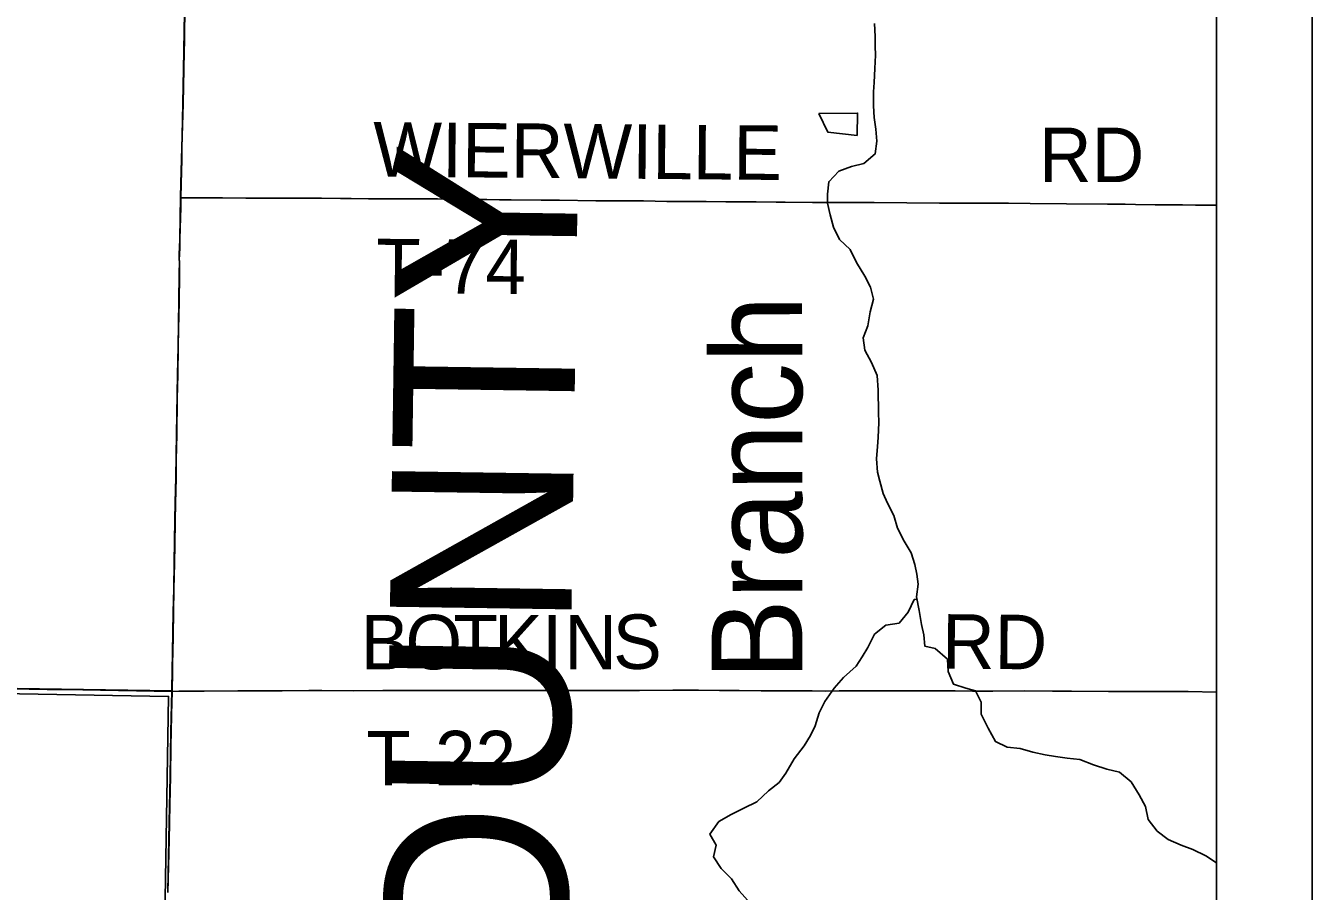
# Model space of a CAD drawing. Extents: x 0 to 34, y 0 to 22.
# Drawn here: x 7.658 to 9, y 19.194 to 20.097 of the extents above; entities that cross this region are included whole.
import ezdxf

# ---------------------------------------------------------------- set-up
doc = ezdxf.new("R2010")
doc.units = 0
for name, color, linetype in [('GM_X_Corporation', 7, 'Continuous'), ('GM_X_County_Road', 7, 'Continuous'), ('GM_X_County_Text', 7, 'Continuous'), ('GM_X_Minor_Lake', 7, 'Continuous'), ('GM_X_Minor_River', 7, 'Continuous'), ('GM_X_Minor_River_Text', 7, 'Continuous'), ('GM_X_Township_Road', 7, 'Continuous'), ('GM_X_Township_Road_Text', 7, 'Continuous'), ('SH_Data', 7, 'Continuous')]:
    doc.layers.add(name, color=color, linetype=linetype)

msp = doc.modelspace()

# ---------------------------------------------------------------- linework, layer by layer
at = {"layer": 'GM_X_Corporation'}
for points in [[(8.9, 14.1), (8.9, 20.4201)], [(8.9, 16.4207), (8.9, 20.4201)], [(6.935, 19.4163), (7.8106, 19.4031), (7.8106, 19.4051), (7.8112, 19.443), (7.812, 19.4853), (7.8125, 19.5095), (7.8131, 19.5368), (7.8137, 19.581), (7.8141, 19.5996), (7.8146, 19.6257), (7.8154, 19.671), (7.8164, 19.7332), (7.817, 19.7624), (7.8178, 19.8096), (7.8183, 19.8376), (7.8185, 19.8513), (7.8181, 19.8532), (7.8181, 19.8549), (7.8181, 19.8598), (7.8186, 19.8654), (7.8188, 19.8747), (7.8194, 19.897), (7.8197, 19.918), (7.82, 19.9325), (7.8207, 19.9579), (7.8212, 19.9822), (7.8219, 20.0157), (7.8232, 20.0704), (7.8235, 20.0928), (7.8238, 20.1089)], [(7.8238, 20.1089), (7.8235, 20.0928), (7.8232, 20.0704), (7.8219, 20.0157), (7.8212, 19.9822), (7.8207, 19.9579), (7.82, 19.9325), (7.8197, 19.918), (7.8194, 19.897), (7.8188, 19.8747), (7.8186, 19.8654), (7.8181, 19.8598), (7.8181, 19.8549), (7.8181, 19.8532), (7.8185, 19.8513), (7.8183, 19.8376), (7.8178, 19.8096), (7.817, 19.7624), (7.8164, 19.7332), (7.8154, 19.671), (7.8146, 19.6257), (7.8141, 19.5996), (7.8137, 19.581), (7.8131, 19.5368), (7.8125, 19.5095), (7.812, 19.4853), (7.8112, 19.443), (7.8106, 19.4051), (7.8106, 19.4031), (7.8096, 19.3604), (7.8087, 19.3138), (7.8077, 19.2659), (7.8062, 19.1933)], [(7.8062, 19.1933), (7.8077, 19.2659), (7.8087, 19.3138), (7.8096, 19.3604), (7.8106, 19.4031), (7.8106, 19.4051), (7.8112, 19.443), (7.812, 19.4853), (7.8125, 19.5095), (7.8131, 19.5368), (7.8137, 19.581), (7.8141, 19.5996), (7.8146, 19.6257), (7.8154, 19.671), (7.8164, 19.7332), (7.817, 19.7624), (7.8178, 19.8096), (7.8183, 19.8376), (7.8185, 19.8513), (7.8181, 19.8532), (7.8181, 19.8549), (7.8181, 19.8598), (7.8186, 19.8654), (7.8188, 19.8747), (7.8194, 19.897), (7.8197, 19.918), (7.82, 19.9325), (7.8207, 19.9579), (7.8212, 19.9822), (7.8219, 20.0157), (7.8232, 20.0704), (7.8235, 20.0928), (7.8238, 20.1089)], [(7.8238, 20.1089), (7.8235, 20.0928), (7.8232, 20.0704), (7.8219, 20.0157), (7.8212, 19.9822), (7.8207, 19.9579), (7.82, 19.9325), (7.8197, 19.918), (7.8194, 19.897), (7.8188, 19.8747), (7.8186, 19.8654), (7.8181, 19.8598), (7.8181, 19.8549), (7.8181, 19.8532), (7.8185, 19.8513), (7.8183, 19.8376), (7.8178, 19.8096), (7.817, 19.7624), (7.8164, 19.7332), (7.8154, 19.671), (7.8146, 19.6257), (7.8141, 19.5996), (7.8137, 19.581), (7.8131, 19.5368), (7.8125, 19.5095), (7.812, 19.4853), (7.8112, 19.443), (7.8106, 19.4051), (7.8106, 19.4031), (7.8096, 19.3604), (7.8087, 19.3138), (7.8077, 19.2659), (7.8062, 19.1933)], [(7.8062, 19.1933), (7.8077, 19.2659), (7.8087, 19.3138), (7.8096, 19.3604), (7.8106, 19.4031), (6.935, 19.4163), (6.733, 19.4196), (6.6989, 19.42), (5.8089, 19.4308), (5.2195, 19.4431), (4.8049, 19.4497), (4.7562, 19.4505)]]:
    msp.add_lwpolyline(points, dxfattribs=at)
msp.add_lwpolyline([(6.7967, 19.4154), (7.8071, 19.3973), (7.7914, 18.4475), (7.7907, 18.396), (6.7843, 18.4413), (6.7907, 19.4159)], close=True, dxfattribs=at)
at = {"layer": 'GM_X_County_Road'}
msp.add_line((7.82, 19.9175), (7.8203, 19.9319), dxfattribs=at)
for points in [[(7.8203, 19.9319), (7.8206, 19.9447), (7.8209, 19.9574), (7.8211, 19.9695), (7.8214, 19.9816), (7.8222, 20.0152), (7.8226, 20.0338), (7.8234, 20.0699), (7.8236, 20.081), (7.8238, 20.0922), (7.8241, 20.1084)], [(7.8108, 19.4025), (7.8112, 19.4232), (7.8113, 19.4329), (7.8115, 19.4425), (7.8118, 19.4611), (7.8122, 19.4847), (7.8127, 19.509), (7.8134, 19.5363), (7.8136, 19.5549), (7.8139, 19.5804), (7.8143, 19.599), (7.8149, 19.6251), (7.8152, 19.6438), (7.8156, 19.6705), (7.8162, 19.7078), (7.8165, 19.7202), (7.8167, 19.7326), (7.8172, 19.7618), (7.8176, 19.7805), (7.8178, 19.7948), (7.8181, 19.809), (7.8186, 19.837), (7.8187, 19.8507), (7.8183, 19.8526), (7.8188, 19.8649), (7.819, 19.8742), (7.8193, 19.8853), (7.8196, 19.8965), (7.8198, 19.907), (7.82, 19.9175)], [(7.8064, 19.1927), (7.8076, 19.2477), (7.808, 19.2654), (7.8084, 19.284), (7.809, 19.3132), (7.8096, 19.3459), (7.8099, 19.3598), (7.8103, 19.3785), (7.8108, 19.4025)]]:
    msp.add_lwpolyline(points, dxfattribs=at)
at = {"layer": 'GM_X_Minor_Lake'}
for points in [[(8.5252, 19.9825), (8.5257, 20.0059), (8.4852, 20.0053)], [(8.4852, 20.0053), (8.4948, 19.9859), (8.5252, 19.9825)]]:
    msp.add_lwpolyline(points, dxfattribs=at)
at = {"layer": 'GM_X_Minor_River'}
for points in [[(8.5435, 20.0994), (8.544, 20.0857), (8.5442, 20.0758), (8.5444, 20.0663), (8.5437, 20.0523), (8.5431, 20.0378), (8.5425, 20.028), (8.5422, 20.0135), (8.5431, 20.0013), (8.5448, 19.9891), (8.5457, 19.9766), (8.544, 19.9633), (8.5323, 19.9533), (8.5193, 19.9501), (8.5062, 19.9454), (8.4957, 19.9342), (8.4943, 19.9213), (8.4945, 19.9118), (8.497, 19.8995), (8.5005, 19.8869), (8.5068, 19.8739), (8.518, 19.8634), (8.5247, 19.85), (8.5335, 19.8357), (8.5394, 19.8242), (8.5423, 19.8116), (8.5389, 19.7984), (8.5364, 19.784), (8.5316, 19.7715), (8.5332, 19.7586), (8.5402, 19.7455), (8.5461, 19.7321), (8.5473, 19.7168), (8.5477, 19.6933), (8.5478, 19.683), (8.5472, 19.6674), (8.5466, 19.6579), (8.5456, 19.645), (8.5465, 19.6313), (8.549, 19.6217), (8.5526, 19.6088), (8.557, 19.5988), (8.5636, 19.5861), (8.5675, 19.5727), (8.5745, 19.5593), (8.5816, 19.547), (8.5855, 19.5347), (8.5876, 19.5248), (8.589, 19.5145), (8.5872, 19.5012), (8.59, 19.4867), (8.5924, 19.4722), (8.5948, 19.4616), (8.5958, 19.4497), (8.6068, 19.4473), (8.6195, 19.436), (8.6201, 19.4234), (8.6259, 19.41), (8.6388, 19.406), (8.6487, 19.4031), (8.6546, 19.3912), (8.6547, 19.3787), (8.6621, 19.3641), (8.6695, 19.3502), (8.6819, 19.3443), (8.6953, 19.3429), (8.7086, 19.3389), (8.7215, 19.3363), (8.7321, 19.3346), (8.7443, 19.3329), (8.7577, 19.3315)], [(8.5877, 19.4988), (8.5848, 19.4982), (8.5785, 19.4851), (8.5691, 19.4738), (8.5553, 19.4714), (8.5433, 19.4621), (8.5366, 19.4482), (8.5307, 19.4384), (8.5244, 19.4287), (8.5112, 19.4171), (8.5014, 19.4059), (8.4916, 19.392), (8.4857, 19.38), (8.4816, 19.3667), (8.4765, 19.3566), (8.4701, 19.3456), (8.4596, 19.3322), (8.4509, 19.3171), (8.4439, 19.3074), (8.433, 19.2988), (8.4206, 19.2873), (8.4071, 19.2807), (8.394, 19.2741), (8.3809, 19.2667), (8.3715, 19.2536), (8.3781, 19.242), (8.3756, 19.2299), (8.3834, 19.2176), (8.3943, 19.2068), (8.4024, 19.1944), (8.414, 19.1813)], [(8.7577, 19.3315), (8.7717, 19.3259), (8.7857, 19.3214), (8.799, 19.3181), (8.811, 19.308), (8.8196, 19.2946), (8.8262, 19.2823), (8.829, 19.2689), (8.8383, 19.2566), (8.8496, 19.248), (8.8632, 19.242), (8.8754, 19.2376), (8.889, 19.2309), (8.9, 19.2236)]]:
    msp.add_lwpolyline(points, dxfattribs=at)
at = {"layer": 'GM_X_Township_Road'}
msp.add_line((7.82, 19.9175), (7.8203, 19.9319), dxfattribs=at)
for points in [[(7.8203, 19.9319), (7.8206, 19.9447), (7.8209, 19.9574), (7.8211, 19.9695), (7.8214, 19.9816), (7.8222, 20.0152), (7.8226, 20.0338), (7.8234, 20.0699), (7.8236, 20.081), (7.8238, 20.0922), (7.8241, 20.1084)], [(7.8108, 19.4025), (7.8112, 19.4232), (7.8113, 19.4329), (7.8115, 19.4425), (7.8118, 19.4611), (7.8122, 19.4847), (7.8127, 19.509), (7.8134, 19.5363), (7.8136, 19.5549), (7.8139, 19.5804), (7.8143, 19.599), (7.8149, 19.6251), (7.8152, 19.6438), (7.8156, 19.6705), (7.8162, 19.7078), (7.8165, 19.7202), (7.8167, 19.7326), (7.8172, 19.7618), (7.8176, 19.7805), (7.8178, 19.7948), (7.8181, 19.809), (7.8186, 19.837), (7.8187, 19.8507), (7.8183, 19.8526), (7.8188, 19.8649), (7.819, 19.8742), (7.8193, 19.8853), (7.8196, 19.8965), (7.8198, 19.907), (7.82, 19.9175)], [(7.82, 19.9175), (7.8273, 19.9175), (7.8285, 19.9175), (7.8391, 19.9174), (7.8503, 19.9175), (7.8633, 19.9174), (7.8876, 19.9171), (7.9205, 19.9171), (7.9373, 19.9171), (7.9441, 19.9171), (7.9559, 19.9171), (7.9665, 19.917), (7.9863, 19.9167), (7.9975, 19.9166), (8.0155, 19.9165), (8.0447, 19.9165), (8.0603, 19.9164), (8.0727, 19.9163), (8.0876, 19.9162), (8.1025, 19.916), (8.1174, 19.9158), (8.1391, 19.9155), (8.1522, 19.9153), (8.1646, 19.9152), (8.1957, 19.915), (8.2149, 19.9149), (8.2528, 19.9144), (8.3025, 19.9142), (8.3267, 19.9137), (8.3479, 19.9136), (8.3678, 19.9135), (8.3883, 19.9134), (8.416, 19.9134)], [(8.416, 19.9134), (8.4199, 19.9134), (8.441, 19.913), (8.4503, 19.9129), (8.4789, 19.9127), (8.4976, 19.9127), (8.5274, 19.9124), (8.5429, 19.9124), (8.5771, 19.9122), (8.6112, 19.9118), (8.6479, 19.912), (8.6684, 19.9119), (8.6833, 19.9117), (8.7056, 19.9114), (8.7435, 19.911), (8.7864, 19.9109), (8.805, 19.9107), (8.8156, 19.9105), (8.8361, 19.9102), (8.8578, 19.9101), (8.8647, 19.91), (8.8783, 19.9098), (8.8888, 19.9097), (8.9, 19.9098)], [(7.6431, 19.4052), (7.6617, 19.4049), (7.6804, 19.4046), (7.699, 19.4043), (7.7177, 19.404), (7.7363, 19.4037), (7.755, 19.4034), (7.7736, 19.4031), (7.7922, 19.4028), (7.8108, 19.4025)], [(7.8108, 19.4025), (7.8179, 19.4026), (7.8441, 19.4027), (7.8795, 19.403), (7.9255, 19.403), (7.9534, 19.4033), (7.9671, 19.4035), (8, 19.4031), (8.0305, 19.4033), (8.0522, 19.4034), (8.1001, 19.4033), (8.1311, 19.4033), (8.2237, 19.4033), (8.2573, 19.4033), (8.2815, 19.4035), (8.2983, 19.4035), (8.3331, 19.4036), (8.3598, 19.4036), (8.3816, 19.4034), (8.4021, 19.4033), (8.4251, 19.4032), (8.445, 19.4031), (8.4785, 19.4029), (8.4928, 19.4028), (8.5065, 19.4029), (8.5226, 19.403), (8.5375, 19.403), (8.5562, 19.4029), (8.6022, 19.403), (8.6276, 19.4029), (8.6456, 19.4027), (8.6668, 19.4026), (8.7003, 19.4029), (8.7289, 19.4027), (8.7488, 19.4027), (8.7873, 19.4025), (8.8221, 19.4024), (8.8482, 19.4023), (8.8706, 19.4022), (8.9, 19.4018)], [(7.8064, 19.1927), (7.8076, 19.2477), (7.808, 19.2654), (7.8084, 19.284), (7.809, 19.3132), (7.8096, 19.3459), (7.8099, 19.3598), (7.8103, 19.3785), (7.8108, 19.4025)]]:
    msp.add_lwpolyline(points, dxfattribs=at)
at = {"layer": 'SH_Data'}
for p, q in [((9, 21), (9, 14)), ((8.9, 20.9), (8.9, 14.1)), ((8.9, 20.9), (8.9, 14.1))]:
    msp.add_line(p, q, dxfattribs=at)

# ---------------------------------------------------------------- texts
at = {"layer": 'GM_X_County_Text'}
msp.add_text('SHELBY COUNTY', height=0.189394, rotation=89.1576, dxfattribs=at).set_placement((8.2031, 17.8348))
at = {"layer": 'GM_X_Minor_River_Text'}
msp.add_text('Branch', height=0.09468, rotation=90.0353, dxfattribs=at).set_placement((8.4682, 19.4143))
at = {"layer": 'GM_X_Township_Road_Text'}
for s, height, rotation, p in [('WIERWILLE', 0.05682, 359.5167, (8.0203, 19.9396)), ('RD', 0.05682, 0, (8.715, 19.9338)), ('T-74', 0.05682, 359.6509, (8.0235, 19.8179)), ('S', 0.0568, 0.9998, (8.2711, 19.4255)), ('B', 0.0568, 0, (8.0075, 19.4255)), ('O', 0.0568, 0, (8.0542, 19.4255)), ('T', 0.0568, 0, (8.1042, 19.4255)), ('K', 0.0568, 0, (8.1467, 19.4255)), ('I', 0.0568, 0, (8.1967, 19.4255)), ('N', 0.0568, 0.0338, (8.22, 19.4255)), ('RD', 0.05682, 359.5026, (8.6136, 19.4263)), ('T-22', 0.05682, 0, (8.0133, 19.3045))]:
    msp.add_text(s, height=height, rotation=rotation, dxfattribs=at).set_placement(p)

doc.saveas('drawing.dxf')
